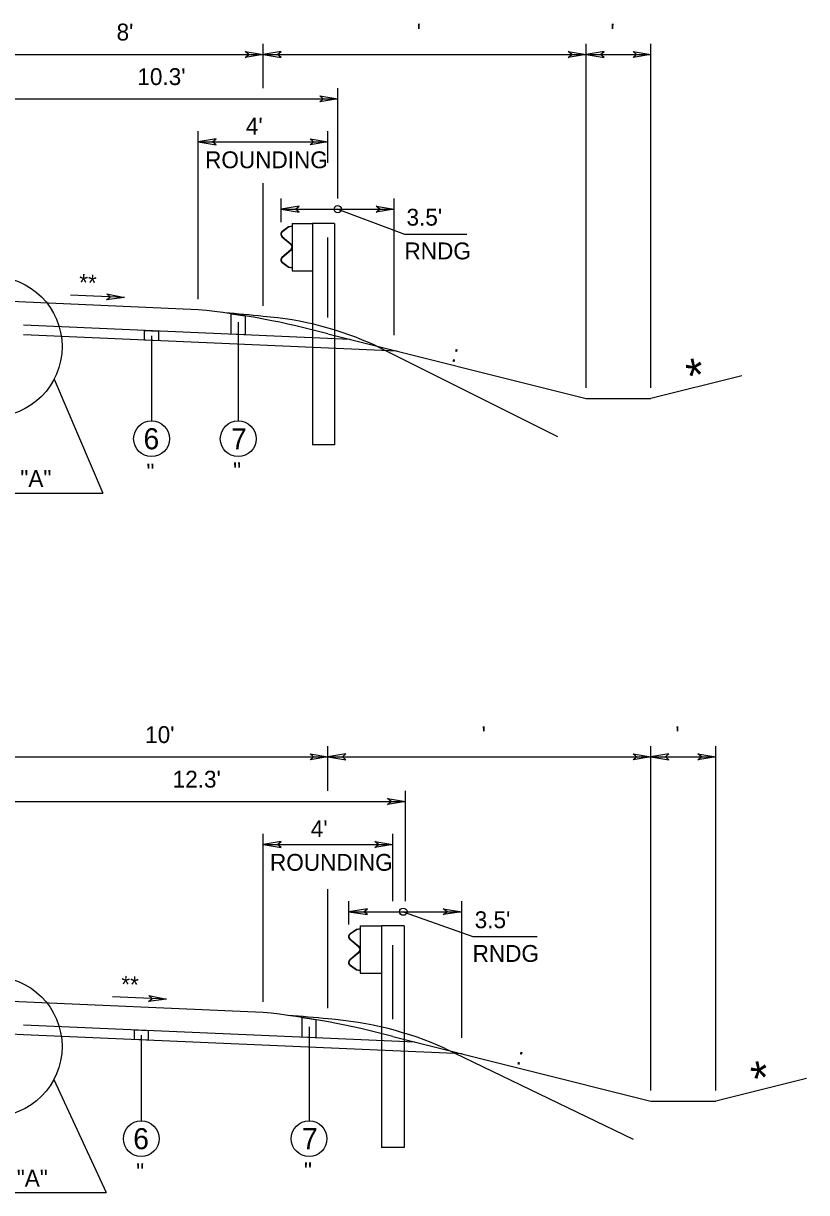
# Model space of a CAD drawing. Extents: x -540 to 1231, y -564 to 421.
# Drawn here: x 1156.5 to 1221.5, y 74.2 to 171.4 of the extents above; entities that cross this region are included whole.
import ezdxf

# ---------------------------------------------------------------- set-up
doc = ezdxf.new("R2010")
doc.units = 0
doc.layers.add('1', color=7, linetype='Continuous')
doc.layers.add('Des_ Drain_ Ftrs', color=7, linetype='Continuous')

msp = doc.modelspace()

# ---------------------------------------------------------------- linework, layer by layer
at = {"layer": '1'}
for p, q in [((1176.39, 165.964), (1176.39, 169.667)), ((1203.213, 141.085), (1203.213, 169.667)), ((1208.601, 141.085), (1208.601, 169.667)), ((1154.837, 168.787), (1176.39, 168.787)), ((1176.39, 168.787), (1203.213, 168.787)), ((1203.213, 168.787), (1208.601, 168.787)), ((1182.585, 156.808), (1182.585, 165.964)), ((1154.835, 165.084), (1182.585, 165.084)), ((1171.002, 148.454), (1171.002, 162.391)), ((1181.778, 159.767), (1181.778, 162.391)), ((1171.002, 161.511), (1181.778, 161.511)), ((1176.39, 147.899), (1176.39, 158.074)), ((1177.893, 154.857), (1177.893, 156.808)), ((1187.277, 145.445), (1187.277, 156.808)), ((1177.893, 155.928), (1187.277, 155.928)), ((1182.585, 155.928), (1188.142, 153.857)), ((1178.491, 154.46), (1177.974, 154.071)), ((1178.806, 154.516), (1178.491, 154.46)), ((1178.806, 154.486), (1178.503, 154.432)), ((1178.806, 154.744), (1178.806, 150.813)), ((1178.806, 154.744), (1180.491, 154.744)), ((1180.491, 154.744), (1180.491, 136.347)), ((1182.316, 154.744), (1180.491, 154.744)), ((1182.316, 154.744), (1182.316, 136.347)), ((1177.959, 153.639), (1178.69, 153.004)), ((1177.978, 153.661), (1178.71, 153.026)), ((1178.503, 154.432), (1177.992, 154.048)), ((1181.778, 146.931), (1181.778, 153.579)), ((1188.142, 153.857), (1193.297, 153.857)), ((1178.69, 152.553), (1177.959, 151.918)), ((1178.71, 152.53), (1177.978, 151.895)), ((1178.776, 152.816), (1178.776, 152.741)), ((1178.806, 152.816), (1178.806, 152.741)), ((1177.974, 151.485), (1178.491, 151.096)), ((1177.992, 151.509), (1178.503, 151.124)), ((1178.491, 151.096), (1178.806, 151.04)), ((1178.503, 151.124), (1178.806, 151.07)), ((1178.806, 150.813), (1180.491, 150.813)), ((1164.886, 148.588), (1160.392, 148.784)), ((1171.002, 147.574), (1154.842, 148.28)), ((1177.893, 146.798), (1177.893, 146.798)), ((1183.611, 145.106), (1156.484, 146.291)), ((1174.322, 146.538), (1174.322, 138.336)), ((1187.531, 144.126), (1156.484, 145.482)), ((1167.126, 145.39), (1167.126, 138.336)), ((1181.778, 145.565), (1203.213, 140.205)), ((1185.777, 144.565), (1200.828, 137.039)), ((1216.136, 142.088), (1208.601, 140.205)), ((1159.037, 141.808), (1163.092, 132.343)), ((1203.213, 140.205), (1208.601, 140.205)), ((1182.316, 136.347), (1180.491, 136.347)), ((1144.306, 132.343), (1163.092, 132.343)), ((1181.778, 107.6), (1181.778, 111.302)), ((1208.602, 82.705), (1208.602, 111.302)), ((1213.99, 82.705), (1213.99, 111.302)), ((1154.837, 110.422), (1181.778, 110.422)), ((1181.778, 110.422), (1208.602, 110.422)), ((1208.602, 110.422), (1213.99, 110.422)), ((1188.208, 98.444), (1188.208, 107.6)), ((1154.838, 106.72), (1188.208, 106.72)), ((1176.39, 90.074), (1176.39, 104.026)), ((1187.166, 98.444), (1187.166, 104.026)), ((1176.39, 103.146), (1187.166, 103.146)), ((1181.778, 89.535), (1181.778, 99.444)), ((1183.516, 96.493), (1183.516, 98.444)), ((1192.9, 87.08), (1192.9, 98.444)), ((1183.516, 97.564), (1192.9, 97.564)), ((1188.033, 97.564), (1193.797, 95.493)), ((1184.462, 96.38), (1184.462, 92.449)), ((1184.462, 96.38), (1186.21, 96.38)), ((1186.21, 96.38), (1186.21, 77.983)), ((1188.104, 96.38), (1186.21, 96.38)), ((1188.104, 96.38), (1188.104, 77.983)), ((1183.584, 95.275), (1184.343, 94.64)), ((1184.136, 96.096), (1183.6, 95.707)), ((1183.604, 95.297), (1184.363, 94.662)), ((1184.149, 96.068), (1183.618, 95.684)), ((1184.462, 96.152), (1184.136, 96.096)), ((1184.462, 96.122), (1184.149, 96.068)), ((1193.797, 95.493), (1199.144, 95.493)), ((1184.432, 94.452), (1184.432, 94.377)), ((1184.462, 94.452), (1184.462, 94.377)), ((1187.166, 88.622), (1187.166, 94.772)), ((1184.343, 94.189), (1183.584, 93.554)), ((1184.363, 94.166), (1183.604, 93.531)), ((1183.6, 93.121), (1184.136, 92.732)), ((1183.618, 93.145), (1184.149, 92.76)), ((1184.136, 92.732), (1184.462, 92.676)), ((1184.149, 92.76), (1184.462, 92.706)), ((1184.462, 92.449), (1186.21, 92.449)), ((1168.381, 90.291), (1163.887, 90.487)), ((1176.39, 89.194), (1154.842, 90.135)), ((1156.484, 87.338), (1122.508, 88.821)), ((1183.516, 88.434), (1183.516, 88.434)), ((1189, 86.727), (1156.484, 88.147)), ((1180.209, 87.986), (1180.209, 80.191)), ((1192.92, 85.746), (1156.484, 87.338)), ((1166.272, 87.316), (1166.272, 80.191)), ((1187.166, 87.185), (1208.602, 81.825)), ((1191.519, 86.2), (1207.132, 78.675)), ((1159.015, 83.621), (1163.369, 74.225)), ((1221.525, 83.709), (1213.99, 81.825)), ((1208.602, 81.825), (1213.99, 81.825)), ((1188.104, 77.983), (1186.21, 77.983)), ((1144.583, 74.225), (1163.369, 74.225))]:
    msp.add_line(p, q, dxfattribs=at)
for points in [[(1173.749, 147.234), (1174.896, 147.057), (1174.896, 145.487), (1173.749, 145.537)], [(1166.553, 145.851), (1167.699, 145.801), (1167.699, 144.992), (1166.553, 145.042)], [(1179.635, 88.78), (1180.782, 88.595), (1180.782, 87.086), (1179.635, 87.136)], [(1165.698, 87.744), (1166.845, 87.694), (1166.845, 86.885), (1165.698, 86.935)]]:
    msp.add_lwpolyline(points, close=True, dxfattribs=at)
for centre, radius in [((1182.585, 155.928), 0.3), ((1153.858, 144.502), 5.838), ((1167.126, 136.851), 1.485), ((1174.322, 136.851), 1.485), ((1153.858, 86.358), 5.838), ((1166.272, 78.706), 1.485), ((1180.209, 78.706), 1.485)]:
    msp.add_circle(centre, radius, dxfattribs=at)
for centre, radius, start, end in [((1178.141, 153.849), 0.278, 126.97989, 229.02099), ((1178.141, 153.849), 0.249, 126.97989, 229.02099), ((1178.527, 152.816), 0.249, 0, 49.03649), ((1178.527, 152.74), 0.249, 310.96352, 0), ((1178.527, 152.816), 0.278, 0, 49.03649), ((1178.527, 152.74), 0.278, 310.96352, 0), ((1178.141, 151.708), 0.278, 130.97902, 233.02011), ((1178.141, 151.708), 0.249, 130.97902, 233.02011), ((1164.117, 80.74), 67.188, 74.76019, 84.11876), ((1165.57, 46.355), 101.244, 83.86333, 85.67746), ((1174.27, 119.733), 27.368, 65.13739, 85.55132), ((1169.505, 22.36), 67.188, 74.76019, 84.11876)]:
    msp.add_arc(centre, radius, start, end, dxfattribs=at)
msp.add_ellipse((1188.033, 97.564), major_axis=(-0.311, 0), ratio=0.964041, dxfattribs=at)
for centre, major_axis, start_param, end_param in [((1183.773, 95.485), (-0.288, 0), 5.35781, 7.138763), ((1183.773, 95.485), (-0.258, 0), 5.35781, 7.138763), ((1184.174, 94.452), (0.258, 0), 0, 0.855848), ((1184.174, 94.376), (0.258, 0), 5.427337, 6.283185), ((1184.174, 94.452), (0.288, 0), 0, 0.855848), ((1184.174, 94.376), (0.288, 0), 5.427337, 6.283185), ((1183.773, 93.344), (-0.288, 0), 5.427608, 7.208561), ((1183.773, 93.344), (-0.258, 0), 5.427608, 7.208561), ((1170.558, -12.009), (105.02, 0), 1.463691, 1.495354), ((1179.583, 61.368), (28.389, 0), 1.136862, 1.493152)]:
    msp.add_ellipse(centre, major_axis=major_axis, ratio=0.964041, start_param=start_param, end_param=end_param, dxfattribs=at)
at = {"layer": 'Des_ Drain_ Ftrs'}
for points in [[(1176.39, 168.787), (1174.901, 168.538), (1175.196, 168.787), (1174.901, 169.035)], [(1176.39, 168.787), (1177.878, 168.538), (1177.583, 168.787), (1177.878, 169.035)], [(1203.213, 168.787), (1201.725, 168.538), (1202.02, 168.787), (1201.725, 169.035)], [(1203.213, 168.787), (1204.701, 168.538), (1204.406, 168.787), (1204.701, 169.035)], [(1208.601, 168.787), (1207.113, 168.538), (1207.408, 168.787), (1207.113, 169.035)], [(1182.585, 165.084), (1181.097, 164.836), (1181.392, 165.084), (1181.097, 165.333)], [(1171.002, 161.511), (1172.49, 161.262), (1172.195, 161.511), (1172.49, 161.759)], [(1181.778, 161.511), (1180.29, 161.262), (1180.585, 161.511), (1180.29, 161.759)], [(1177.893, 155.928), (1179.381, 155.68), (1179.086, 155.928), (1179.381, 156.177)], [(1187.277, 155.928), (1185.789, 155.68), (1186.084, 155.928), (1185.789, 156.177)], [(1164.886, 148.588), (1163.388, 148.404), (1163.694, 148.639), (1163.41, 148.9)], [(1181.778, 110.422), (1180.29, 110.174), (1180.585, 110.422), (1180.29, 110.671)], [(1181.778, 110.422), (1183.266, 110.174), (1182.971, 110.422), (1183.266, 110.671)], [(1208.602, 110.422), (1207.113, 110.174), (1207.408, 110.422), (1207.113, 110.671)], [(1208.602, 110.422), (1210.09, 110.174), (1209.795, 110.422), (1210.09, 110.671)], [(1213.99, 110.422), (1212.502, 110.174), (1212.797, 110.422), (1212.502, 110.671)], [(1188.208, 106.72), (1186.718, 106.472), (1187.013, 106.72), (1186.718, 106.969)], [(1176.39, 103.146), (1177.878, 102.898), (1177.583, 103.146), (1177.878, 103.395)], [(1187.166, 103.146), (1185.678, 102.898), (1185.973, 103.146), (1185.678, 103.395)], [(1183.516, 97.564), (1185.06, 97.316), (1184.754, 97.564), (1185.06, 97.813)], [(1192.9, 97.564), (1191.356, 97.316), (1191.662, 97.564), (1191.356, 97.813)], [(1168.381, 90.291), (1166.884, 90.106), (1167.189, 90.342), (1166.905, 90.603)]]:
    msp.add_lwpolyline(points, close=True, dxfattribs=at)

# ---------------------------------------------------------------- texts
at = {"layer": '1'}
for s, height, p in [("8'", 1.4, (1164.223, 169.938)), ("  '", 1.4, (1188.105, 169.938)), (" '", 1.4, (1204.712, 169.938)), ("10.3'", 1.4, (1165.948, 166.235)), ("4'", 1.4, (1174.961, 162.126)), ('ROUNDING', 1.4, (1171.572, 159.326)), ("3.5'", 1.4, (1188.301, 154.557)), ('RNDG', 1.4, (1188.132, 151.757)), ('6', 1.75, (1166.461, 135.976)), ('7', 1.75, (1173.731, 135.976)), ('SEE DETAIL "A"', 1.4, (1144.89, 132.847)), (' "', 1.4, (1166.182, 133.395)), (' "', 1.4, (1173.378, 133.491)), ("10'", 1.4, (1166.592, 111.574)), ("  '", 1.4, (1193.494, 111.574)), (" '", 1.4, (1210.101, 111.574)), ("12.3'", 1.4, (1168.879, 107.871)), ("4'", 1.4, (1180.349, 103.762)), ('ROUNDING', 1.4, (1176.96, 100.962)), ("3.5'", 1.4, (1193.962, 96.193)), ('RNDG', 1.4, (1193.786, 93.393)), ('6', 1.75, (1165.607, 77.831)), ('7', 1.75, (1179.618, 77.831)), (' "', 1.4, (1179.265, 75.347)), ('SEE DETAIL "A"', 1.4, (1144.592, 74.728)), (' "', 1.4, (1165.328, 75.25))]:
    msp.add_text(s, height=height, dxfattribs=at).set_placement(p)
for s, height, rotation, p in [('**', 1.4, 357.2167, (1161.072, 149.149)), (' : ', 1.4, 345.77179, (1191.446, 143.437)), ('*', 2.8, 12.84793, (1211.916, 140.61)), ('**', 1.4, 357.21677, (1164.567, 90.852)), (' : ', 1.4, 345.77179, (1196.834, 85.057)), ('*', 2.8, 12.84793, (1217.305, 82.23))]:
    msp.add_text(s, height=height, rotation=rotation, dxfattribs=at).set_placement(p)

doc.saveas('drawing.dxf')
